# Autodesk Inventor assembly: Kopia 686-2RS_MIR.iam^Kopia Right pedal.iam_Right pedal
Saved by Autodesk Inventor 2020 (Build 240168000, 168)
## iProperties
Created: 2017-10
Part Number: Kopia 686-2RS_MIR.iam^Kopia Right pedal.iam_Right pedal
Material: Ogólny
Document SubType Name: Assembly
Designer: Tomasz
Sending System: SolidWorks 2017
Last Author: Tomasz
Last Saved: 2017-10-01
Author: Tomasz
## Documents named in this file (13)
- C:\Users\bruno\Documents\1-Cours-2020-21\1STI2D-2020-21\IT\6. Antivol\Inventor-Antivol\INVENTOR 2018_Steel Hardtail B+\Kopia 686-2RS_MIR.iam^Kopia Right pedal.iam_Right pedal.iam
- C:\Users\bruno\Documents\1-Cours-2020-21\1STI2D-2020-21\IT\6. Antivol\Inventor-Antivol\INVENTOR 2018_Steel Hardtail B+\Kopia 686-2Z_12_MIR.ipt^Kopia 686-2RS_MIR.iam_Kopia Right pedal.iam_Right pedal.ipt
- C:\Users\bruno\Documents\1-Cours-2020-21\1STI2D-2020-21\IT\6. Antivol\Inventor-Antivol\INVENTOR 2018_Steel Hardtail B+\Kopia 686-2Z_11_MIR.ipt^Kopia 686-2RS_MIR.iam_Kopia Right pedal.iam_Right pedal.ipt
- C:\Users\bruno\Documents\1-Cours-2020-21\1STI2D-2020-21\IT\6. Antivol\Inventor-Antivol\INVENTOR 2018_Steel Hardtail B+\Kopia 686-2Z_10_MIR.ipt^Kopia 686-2RS_MIR.iam_Kopia Right pedal.iam_Right pedal.ipt
- C:\Users\bruno\Documents\1-Cours-2020-21\1STI2D-2020-21\IT\6. Antivol\Inventor-Antivol\INVENTOR 2018_Steel Hardtail B+\Kopia 686-2Z_09_MIR.ipt^Kopia 686-2RS_MIR.iam_Kopia Right pedal.iam_Right pedal.ipt
- C:\Users\bruno\Documents\1-Cours-2020-21\1STI2D-2020-21\IT\6. Antivol\Inventor-Antivol\INVENTOR 2018_Steel Hardtail B+\Kopia 686-2Z_08_MIR.ipt^Kopia 686-2RS_MIR.iam_Kopia Right pedal.iam_Right pedal.ipt
- C:\Users\bruno\Documents\1-Cours-2020-21\1STI2D-2020-21\IT\6. Antivol\Inventor-Antivol\INVENTOR 2018_Steel Hardtail B+\Kopia 686-2Z_07_MIR.ipt^Kopia 686-2RS_MIR.iam_Kopia Right pedal.iam_Right pedal.ipt
- C:\Users\bruno\Documents\1-Cours-2020-21\1STI2D-2020-21\IT\6. Antivol\Inventor-Antivol\INVENTOR 2018_Steel Hardtail B+\Kopia 686-2Z_06_MIR.ipt^Kopia 686-2RS_MIR.iam_Kopia Right pedal.iam_Right pedal.ipt
- C:\Users\bruno\Documents\1-Cours-2020-21\1STI2D-2020-21\IT\6. Antivol\Inventor-Antivol\INVENTOR 2018_Steel Hardtail B+\Kopia 686-2Z_05_MIR.ipt^Kopia 686-2RS_MIR.iam_Kopia Right pedal.iam_Right pedal.ipt
- C:\Users\bruno\Documents\1-Cours-2020-21\1STI2D-2020-21\IT\6. Antivol\Inventor-Antivol\INVENTOR 2018_Steel Hardtail B+\Kopia 686-2Z_04_MIR.ipt^Kopia 686-2RS_MIR.iam_Kopia Right pedal.iam_Right pedal.ipt
- C:\Users\bruno\Documents\1-Cours-2020-21\1STI2D-2020-21\IT\6. Antivol\Inventor-Antivol\INVENTOR 2018_Steel Hardtail B+\Kopia 686-2Z_03_MIR.ipt^Kopia 686-2RS_MIR.iam_Kopia Right pedal.iam_Right pedal.ipt
- C:\Users\bruno\Documents\1-Cours-2020-21\1STI2D-2020-21\IT\6. Antivol\Inventor-Antivol\INVENTOR 2018_Steel Hardtail B+\Kopia 686-2Z_02_MIR.ipt^Kopia 686-2RS_MIR.iam_Kopia Right pedal.iam_Right pedal.ipt
- C:\Users\bruno\Documents\1-Cours-2020-21\1STI2D-2020-21\IT\6. Antivol\Inventor-Antivol\INVENTOR 2018_Steel Hardtail B+\Kopia 686-2Z_01_MIR.ipt^Kopia 686-2RS_MIR.iam_Kopia Right pedal.iam_Right pedal.ipt
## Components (12 placed, 12 different names)
1. Kopia 686-2Z_12_MIR.ipt^Kopia 686-2RS_MIR.iam_Kopia Right pedal.iam_Right pedal:1
2. Kopia 686-2Z_11_MIR.ipt^Kopia 686-2RS_MIR.iam_Kopia Right pedal.iam_Right pedal:1
3. Kopia 686-2Z_10_MIR.ipt^Kopia 686-2RS_MIR.iam_Kopia Right pedal.iam_Right pedal:1
4. Kopia 686-2Z_09_MIR.ipt^Kopia 686-2RS_MIR.iam_Kopia Right pedal.iam_Right pedal:1
5. Kopia 686-2Z_08_MIR.ipt^Kopia 686-2RS_MIR.iam_Kopia Right pedal.iam_Right pedal:1
6. Kopia 686-2Z_07_MIR.ipt^Kopia 686-2RS_MIR.iam_Kopia Right pedal.iam_Right pedal:1
7. Kopia 686-2Z_06_MIR.ipt^Kopia 686-2RS_MIR.iam_Kopia Right pedal.iam_Right pedal:1
8. Kopia 686-2Z_05_MIR.ipt^Kopia 686-2RS_MIR.iam_Kopia Right pedal.iam_Right pedal:1
9. Kopia 686-2Z_04_MIR.ipt^Kopia 686-2RS_MIR.iam_Kopia Right pedal.iam_Right pedal:1
10. Kopia 686-2Z_03_MIR.ipt^Kopia 686-2RS_MIR.iam_Kopia Right pedal.iam_Right pedal:1
11. Kopia 686-2Z_02_MIR.ipt^Kopia 686-2RS_MIR.iam_Kopia Right pedal.iam_Right pedal:1
12. Kopia 686-2Z_01_MIR.ipt^Kopia 686-2RS_MIR.iam_Kopia Right pedal.iam_Right pedal:1
